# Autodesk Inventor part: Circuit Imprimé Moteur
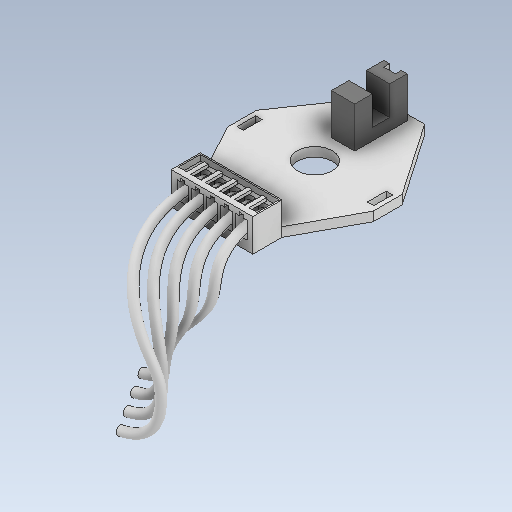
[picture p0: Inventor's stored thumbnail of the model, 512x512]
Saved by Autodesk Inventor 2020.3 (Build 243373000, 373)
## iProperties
Created: 2018-09
Part Number: Circuit Imprimé Moteur
Material: Générique
Document SubType Name: Modeling
Designer: ficho
Density: 1 g/cm^3
Appearance: Par défaut
Mass: 1.49039 g
Surface Area: 27.4173 cm^2
Volume: 1.49039 cm^3
Sending System: SolidWorks 2015
Last Author: adrien
Last Saved: 2019-01-11
Author: ficho
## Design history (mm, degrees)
feature "Balayage1"
node "Solide1"
